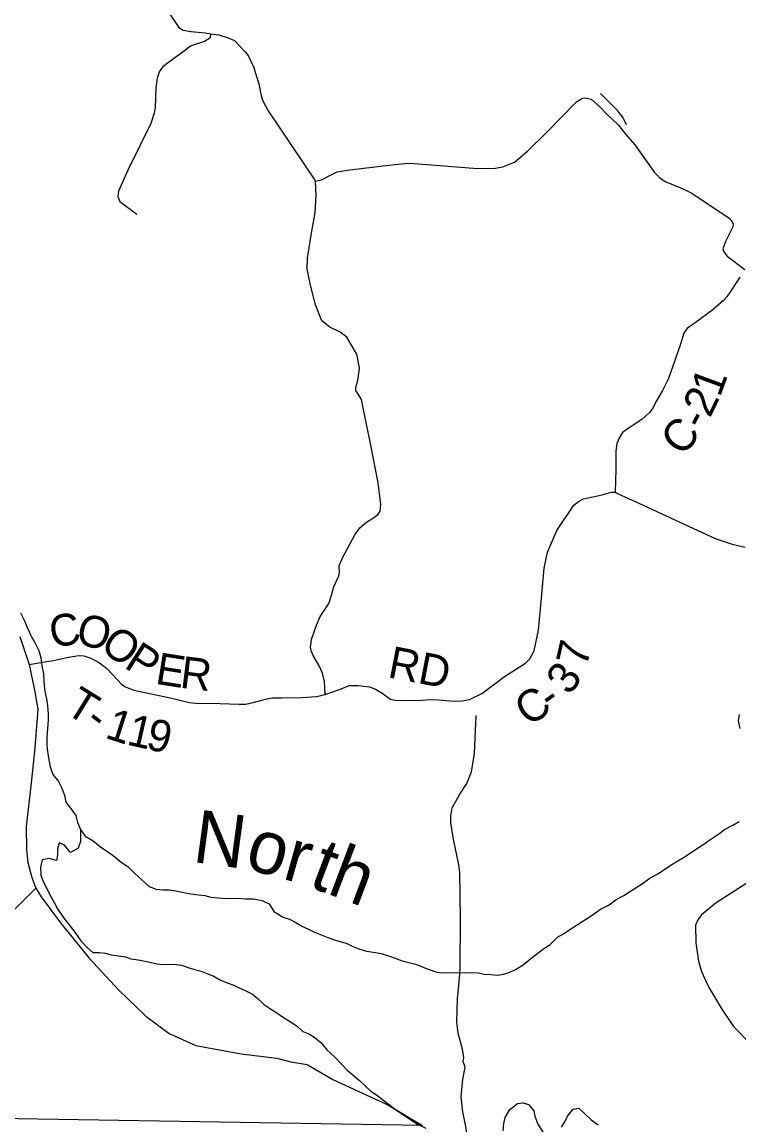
# Model space of a CAD drawing. Extents: x -22 to 431, y -18 to 160.
# Drawn here: x 5.232 to 6.515, y 17.007 to 18.98 of the extents above; entities that cross this region are included whole.
import ezdxf

# ---------------------------------------------------------------- set-up
doc = ezdxf.new("R2010")
doc.units = 0
for name, color, linetype in [('GM_X_Adjacent_County_Text', 7, 'Continuous'), ('GM_X_City_Street', 7, 'Continuous'), ('GM_X_City_Street_Text', 7, 'Continuous'), ('GM_X_County_Road', 7, 'Continuous'), ('GM_X_Major_River', 7, 'Continuous'), ('GM_X_Major_River_Text', 7, 'Continuous'), ('GM_X_Minor_River', 7, 'Continuous'), ('GM_X_Minor_River_Text', 7, 'Continuous'), ('GM_X_Rail_Line', 7, 'Continuous')]:
    doc.layers.add(name, color=color, linetype=linetype)

msp = doc.modelspace()

# ---------------------------------------------------------------- linework, layer by layer
at = {"layer": 'GM_X_Adjacent_County_Text'}
for points in [[(5.4904, 19.0026), (5.5122, 18.97), (5.5202, 18.9649), (5.5339, 18.9625), (5.5597, 18.9603), (5.5695, 18.9585), (5.5836, 18.9565), (5.6003, 18.9515), (5.6118, 18.9464), (5.6214, 18.9367), (5.6311, 18.9266), (5.6369, 18.9184), (5.6459, 18.8996), (5.6555, 18.8694), (5.6597, 18.8479), (5.6625, 18.8388), (5.6719, 18.8208), (5.7569, 18.6949), (5.7676, 18.6977), (5.7871, 18.7076), (5.7958, 18.7115), (5.8135, 18.7149), (5.888, 18.7238), (5.9167, 18.7266), (5.9254, 18.7275), (6.0395, 18.7182), (6.0752, 18.7177), (6.0921, 18.7206), (6.1128, 18.729), (6.1363, 18.7487), (6.1717, 18.7831), (6.2238, 18.8368), (6.2347, 18.8434), (6.2404, 18.8439), (6.2503, 18.8414), (6.266, 18.8277), (6.278, 18.8149), (6.299, 18.7954), (6.3124, 18.7784), (6.3281, 18.7599), (6.3638, 18.7104), (6.3725, 18.7014), (6.3828, 18.6946), (6.4099, 18.683), (6.4194, 18.6789), (6.4304, 18.6733), (6.4971, 18.6286), (6.5028, 18.6226), (6.5044, 18.618), (6.5037, 18.6131), (6.4913, 18.5884), (6.4861, 18.5743), (6.4869, 18.5701), (6.493, 18.5614), (6.4934, 18.5612)], [(6.4934, 18.5612), (6.4938, 18.5608), (6.5255, 18.537)], [(6.5165, 18.5236), (6.5018, 18.5015), (6.4928, 18.4882), (6.4872, 18.4817), (6.4679, 18.4648), (6.4362, 18.4415), (6.4227, 18.4319), (6.4196, 18.4288), (6.4159, 18.4231), (6.4103, 18.4037), (6.401, 18.3779), (6.3925, 18.352), (6.388, 18.3409), (6.3779, 18.3204), (6.3671, 18.3021), (6.3592, 18.2872), (6.3547, 18.2811), (6.3411, 18.2689), (6.3253, 18.2589), (6.3143, 18.2512), (6.3064, 18.2455), (6.3012, 18.2364), (6.2963, 18.2261), (6.2941, 18.2124), (6.2944, 18.1794), (6.2931, 18.1391), (6.2985, 18.1361), (6.3358, 18.119), (6.4245, 18.0778), (6.4724, 18.0562), (6.5024, 18.0457), (6.526, 18.0402)], [(6.0558, 17.7793), (6.0666, 17.7875), (6.0778, 17.796), (6.0954, 17.8089), (6.1149, 17.8217), (6.1328, 17.833), (6.1407, 17.8408), (6.1484, 17.8549), (6.1557, 17.8922), (6.1609, 17.9428), (6.1659, 18.0028), (6.1718, 18.0314), (6.1886, 18.0703), (6.2192, 18.1153), (6.2275, 18.1219), (6.2365, 18.127), (6.2701, 18.134), (6.2859, 18.1387), (6.2931, 18.1391)], [(6.0213, 17.1204), (6.0212, 17.1205), (6.0221, 17.1278), (6.0202, 17.143), (6.0122, 17.1711), (6.0095, 17.1915), (6.011, 17.2321), (6.0144, 17.2697), (6.0155, 17.2871), (6.0162, 17.3766), (6.015, 17.4585), (6.0135, 17.4725), (6.0036, 17.5184), (5.999, 17.548), (5.999, 17.5601), (6.0017, 17.5741), (6.0153, 17.5988), (6.0274, 17.6178), (6.0361, 17.6387), (6.0417, 17.6713), (6.0443, 17.7392)], [(6.5153, 17.7411), (6.5131, 17.7297), (6.5166, 17.7164)], [(6.5288, 17.4398), (6.4737, 17.4042), (6.448, 17.3827), (6.4413, 17.3743), (6.4372, 17.3644), (6.4378, 17.3329), (6.4426, 17.3003), (6.4476, 17.2814), (6.4604, 17.2542), (6.4842, 17.2145), (6.5049, 17.1831), (6.5362, 17.1519)], [(5.0559, 17.0045), (5.0558, 17.0052), (5.0556, 17.0211), (5.056, 17.0485), (5.0617, 17.0756), (5.0678, 17.1416), (5.0671, 17.1579), (5.0705, 17.1754), (5.0781, 17.1936), (5.0867, 17.2088), (5.0966, 17.2213), (5.1072, 17.2342), (5.1249, 17.2638), (5.1318, 17.2756), (5.1393, 17.3025), (5.1548, 17.3401), (5.1718, 17.3613), (5.1862, 17.3743), (5.1983, 17.3788), (5.207, 17.3838), (5.215, 17.3898), (5.2335, 17.4081), (5.2562, 17.4309)], [(6.0299, 16.9577), (6.0285, 16.9883), (6.0261, 17.0043), (6.0204, 17.0309), (6.0175, 17.0577), (6.0208, 17.0892), (6.0247, 17.1107), (6.0213, 17.1204)]]:
    msp.add_lwpolyline(points, dxfattribs=at)
at = {"layer": 'GM_X_County_Road'}
msp.add_lwpolyline([(5.774, 17.7768), (5.7728, 17.8003), (5.7693, 17.8151), (5.7635, 17.8283), (5.7528, 17.8468), (5.7489, 17.8551), (5.7478, 17.8619), (5.7496, 17.8756), (5.7585, 17.9007), (5.7652, 17.9163), (5.7764, 17.9331), (5.7813, 17.9411), (5.7853, 17.9548), (5.7898, 17.9696), (5.7984, 17.989), (5.7998, 17.9955), (5.7994, 18.0068), (5.8049, 18.0217), (5.8274, 18.0628), (5.836, 18.075), (5.848, 18.085), (5.8627, 18.0942), (5.8691, 18.0996), (5.8725, 18.1049), (5.8739, 18.117), (5.8687, 18.1553), (5.8549, 18.2288), (5.8447, 18.2776), (5.8389, 18.3045), (5.8343, 18.3121), (5.8293, 18.3208), (5.8292, 18.3261), (5.8333, 18.3416), (5.8354, 18.3614), (5.8311, 18.3856), (5.8215, 18.4015), (5.8127, 18.4162), (5.8008, 18.4248), (5.7822, 18.4338), (5.7681, 18.4454), (5.7569, 18.4738), (5.7476, 18.509), (5.7417, 18.5374), (5.7427, 18.5571), (5.7499, 18.6019), (5.7561, 18.6388), (5.7581, 18.6695), (5.7569, 18.6949)], dxfattribs=at)
at = {"layer": 'GM_X_Major_River_Text'}
msp.add_line((5.9484, 17.006), (5.0556, 17.0211), dxfattribs=at)
at = {"layer": 'GM_X_Minor_River'}
for points in [[(6.3135, 18.7958), (6.3075, 18.8084), (6.2975, 18.8212), (6.2848, 18.834), (6.2667, 18.8521)], [(5.2288, 17.9229), (5.2357, 17.9085), (5.2406, 17.8968), (5.2479, 17.8816), (5.2551, 17.8688), (5.2616, 17.8555), (5.2654, 17.8423), (5.2669, 17.8282), (5.27, 17.8142), (5.2704, 17.8013), (5.272, 17.7866), (5.2735, 17.7771), (5.2758, 17.7661), (5.2774, 17.7563), (5.2786, 17.7426), (5.2782, 17.7324), (5.2779, 17.7225), (5.2764, 17.7093), (5.276, 17.6983), (5.2757, 17.6888), (5.2768, 17.6793), (5.2784, 17.6672), (5.2799, 17.6573), (5.2819, 17.6475), (5.2868, 17.6342), (5.2967, 17.6214), (5.3024, 17.6104), (5.3074, 17.5972), (5.3097, 17.5847), (5.3181, 17.5737), (5.3276, 17.5605), (5.331, 17.548), (5.336, 17.5358), (5.336, 17.5139), (5.3319, 17.5021), (5.3183, 17.4945), (5.3076, 17.5073), (5.2978, 17.5115), (5.2952, 17.5001), (5.2948, 17.4898), (5.2933, 17.4804), (5.2801, 17.4837), (5.2676, 17.4814)], [(5.336, 17.5355), (5.3447, 17.5237), (5.3587, 17.5151), (5.372, 17.5045), (5.3849, 17.4958), (5.3948, 17.489), (5.4088, 17.477), (5.421, 17.4694), (5.4335, 17.457), (5.4468, 17.4449), (5.4593, 17.4335), (5.4714, 17.429), (5.4836, 17.4279), (5.4957, 17.4276), (5.507, 17.4261), (5.5214, 17.4231), (5.5336, 17.4205), (5.5472, 17.4187), (5.5589, 17.4176), (5.5696, 17.4146), (5.5832, 17.4131), (5.5961, 17.4124), (5.6176, 17.4125), (5.6317, 17.4118), (5.646, 17.4114), (5.6616, 17.4088), (5.6741, 17.4024), (5.6825, 17.3888), (5.6992, 17.379), (5.7101, 17.3753), (5.7219, 17.3692), (5.7321, 17.3628), (5.7443, 17.3576), (5.7549, 17.3519), (5.767, 17.347), (5.7788, 17.3425), (5.7909, 17.338), (5.8004, 17.3354), (5.8117, 17.332), (5.8224, 17.3267), (5.8345, 17.3219), (5.8481, 17.3177), (5.864, 17.3155), (5.8743, 17.3137), (5.8894, 17.3092), (5.8993, 17.3054), (5.9118, 17.3005), (5.9262, 17.2972), (5.9357, 17.2945), (5.9584, 17.2855), (5.974, 17.2803), (5.9838, 17.2795), (6.0145, 17.2796), (6.0258, 17.2793), (6.0364, 17.2797), (6.0486, 17.279), (6.058, 17.2771), (6.0705, 17.276), (6.0834, 17.2753), (6.0936, 17.2769), (6.1035, 17.2799), (6.1148, 17.2849), (6.1284, 17.2937), (6.1424, 17.3047), (6.1545, 17.3146), (6.1654, 17.323), (6.176, 17.3295), (6.19, 17.3428), (6.2006, 17.3489), (6.2123, 17.3565), (6.227, 17.366), (6.2436, 17.3767), (6.2538, 17.3836), (6.2671, 17.3931), (6.2827, 17.4006)], [(6.2827, 17.4006), (6.2949, 17.4101), (6.3088, 17.4175), (6.3227, 17.4263), (6.3347, 17.4344), (6.3445, 17.441), (6.3551, 17.4483), (6.3705, 17.4571), (6.3818, 17.4648), (6.3915, 17.4714), (6.4051, 17.4795), (6.4156, 17.4853), (6.4254, 17.4918), (6.4371, 17.4995), (6.4502, 17.5084), (6.4608, 17.5161), (6.4788, 17.528), (6.489, 17.5357), (6.5036, 17.5434), (6.5149, 17.55)], [(5.2676, 17.4814), (5.2646, 17.4681), (5.2654, 17.4537), (5.2688, 17.4435), (5.2829, 17.4155), (5.289, 17.4049), (5.2951, 17.3936), (5.3054, 17.3788), (5.3134, 17.3678), (5.3263, 17.352), (5.3369, 17.3365), (5.3483, 17.3247), (5.3582, 17.3153), (5.3703, 17.3153), (5.3805, 17.3142), (5.3911, 17.3116), (5.404, 17.3094), (5.4169, 17.3079), (5.4264, 17.3045), (5.4396, 17.3027), (5.4578, 17.299), (5.4726, 17.2956), (5.4847, 17.2941), (5.4946, 17.2945), (5.5074, 17.2942), (5.5169, 17.2927), (5.529, 17.2886), (5.5404, 17.2852), (5.5522, 17.2822), (5.5639, 17.2777), (5.5734, 17.274), (5.587, 17.2664), (5.6003, 17.2608), (5.6109, 17.257), (5.6212, 17.2518), (5.631, 17.2476), (5.6439, 17.2412), (5.6542, 17.2329), (5.664, 17.2231), (5.6762, 17.2148), (5.6875, 17.2076), (5.6993, 17.1993), (5.7118, 17.1918), (5.7243, 17.1839), (5.7342, 17.1744), (5.746, 17.1696), (5.7562, 17.1628), (5.7661, 17.1548), (5.7775, 17.1412), (5.7911, 17.1288), (5.8022, 17.1171), (5.8143, 17.1046), (5.8238, 17.097), (5.8356, 17.0865), (5.8458, 17.077), (5.8565, 17.0668), (5.8663, 17.0612), (5.8796, 17.0502), (5.9039, 17.0321), (5.9134, 17.0257), (5.9259, 17.0178), (5.9395, 17.0087), (5.9543, 17.0012)], [(6.0926, 16.9967), (6.094, 17.01), (6.0963, 17.0206), (6.1049, 17.0351), (6.1185, 17.0454), (6.1284, 17.0469), (6.1379, 17.0439), (6.1474, 17.0326), (6.1496, 17.0227), (6.1546, 17.0083), (6.1649, 16.9924)], [(6.1974, 17.0032), (6.2031, 17.0127), (6.2076, 17.0229), (6.2181, 17.0355), (6.228, 17.0374), (6.2386, 17.0272), (6.25, 17.0166), (6.2625, 17.0072)]]:
    msp.add_lwpolyline(points, dxfattribs=at)
at = {"layer": 'GM_X_Minor_River_Text'}
for points in [[(5.5695, 18.9585), (5.5674, 18.9509), (5.558, 18.9451), (5.5396, 18.9387), (5.5332, 18.9363), (5.5224, 18.9281), (5.4939, 18.9071), (5.4835, 18.8993), (5.4779, 18.892), (5.4732, 18.8794), (5.4712, 18.8616), (5.47, 18.8259), (5.4678, 18.8168), (5.4621, 18.7984), (5.4438, 18.7606), (5.4211, 18.7146), (5.4044, 18.6772), (5.403, 18.6677), (5.4066, 18.6586), (5.4369, 18.636)], [(5.2445, 17.8306), (5.2689, 17.8346), (5.2871, 17.8376), (5.3146, 17.8437), (5.3335, 17.8467), (5.3422, 17.8461), (5.3548, 17.8418), (5.3701, 17.8337), (5.3835, 17.8234), (5.4024, 17.8032), (5.4101, 17.7946), (5.417, 17.7906), (5.4315, 17.7848), (5.4965, 17.7711), (5.5311, 17.7627), (5.5429, 17.7617), (5.5857, 17.761), (5.6202, 17.7597), (5.6323, 17.7599), (5.6474, 17.7632), (5.67, 17.7693), (5.6798, 17.771), (5.6965, 17.7713), (5.7325, 17.7716), (5.7589, 17.7732), (5.774, 17.7768), (5.803, 17.7869), (5.8173, 17.7932), (5.834, 17.7931), (5.8533, 17.7908), (5.864, 17.7865), (5.8762, 17.7791), (5.8912, 17.7688), (5.8988, 17.7666), (5.9143, 17.7661), (5.9473, 17.7671), (5.9632, 17.7678), (5.9764, 17.7673), (6.0052, 17.7651), (6.0193, 17.7658), (6.0325, 17.7683), (6.0558, 17.7793)]]:
    msp.add_lwpolyline(points, dxfattribs=at)
at = {"layer": 'GM_X_Rail_Line'}
msp.add_lwpolyline([(5.2276, 17.8808), (5.2445, 17.8306), (5.2538, 17.7846), (5.2597, 17.7509), (5.2542, 17.6817), (5.248, 17.6183), (5.2388, 17.5408), (5.2394, 17.4983), (5.2421, 17.4767), (5.249, 17.4498), (5.2562, 17.4309), (5.2657, 17.4149), (5.3006, 17.3684), (5.352, 17.3056), (5.405, 17.2485), (5.4533, 17.2017), (5.4948, 17.1707), (5.5427, 17.1493), (5.6236, 17.1341), (5.6874, 17.1269), (5.7124, 17.1202), (5.742, 17.1154), (5.7881, 17.0882), (5.8865, 17.0433), (5.9484, 17.006)], dxfattribs=at)

# ---------------------------------------------------------------- texts
at = {"layer": 'GM_X_City_Street'}
for s, rotation, p in [('1', 69.6432, (6.4805, 18.3073)), ('2', 63.873, (6.4627, 18.2702)), ('C', 49.3923, (6.4129, 18.201)), ('-', 62.5198, (6.4512, 18.2481)), ('7', 77.0313, (6.242, 17.8244)), ('3', 54.5647, (6.2118, 17.7738)), ('C', 33.6608, (6.1379, 17.7186)), ('-', 35.8265, (6.1787, 17.7458))]:
    msp.add_text(s, height=0.0568, rotation=rotation, dxfattribs=at).set_placement(p)
at = {"layer": 'GM_X_City_Street_Text'}
for s, height, rotation, p in [('C', 0.0568, 10.7848, (5.2862, 17.8596)), ('O', 0.0568, 346.2703, (5.3257, 17.8685)), ('O', 0.0568, 322.7717, (5.3687, 17.8593)), ('P', 0.0568, 327.2161, (5.4125, 17.8263)), ('E', 0.0568, 350.9304, (5.4685, 17.7964)), ('RD', 0.05682, 349.0774, (5.8843, 17.8081)), ('R', 0.0568, 353.0718, (5.5128, 17.7894)), ('T', 0.0568, 328.1205, (5.3062, 17.7455)), ('-', 0.0568, 322.6789, (5.3411, 17.7238)), ('1', 0.0568, 342.1147, (5.3782, 17.7)), ('1', 0.0568, 347.241, (5.4169, 17.6878)), ('9', 0.0568, 347.507, (5.4513, 17.68))]:
    msp.add_text(s, height=height, rotation=rotation, dxfattribs=at).set_placement(p)
at = {"layer": 'GM_X_Major_River'}
for s, height, rotation, p in [('N', 0.0947, 352.2931, (5.5349, 17.4777)), ('or', 0.09469, 344.2938, (5.6273, 17.4672)), ('th', 0.09469, 339.2942, (5.7422, 17.4342))]:
    msp.add_text(s, height=height, rotation=rotation, dxfattribs=at).set_placement(p)

doc.saveas('drawing.dxf')
